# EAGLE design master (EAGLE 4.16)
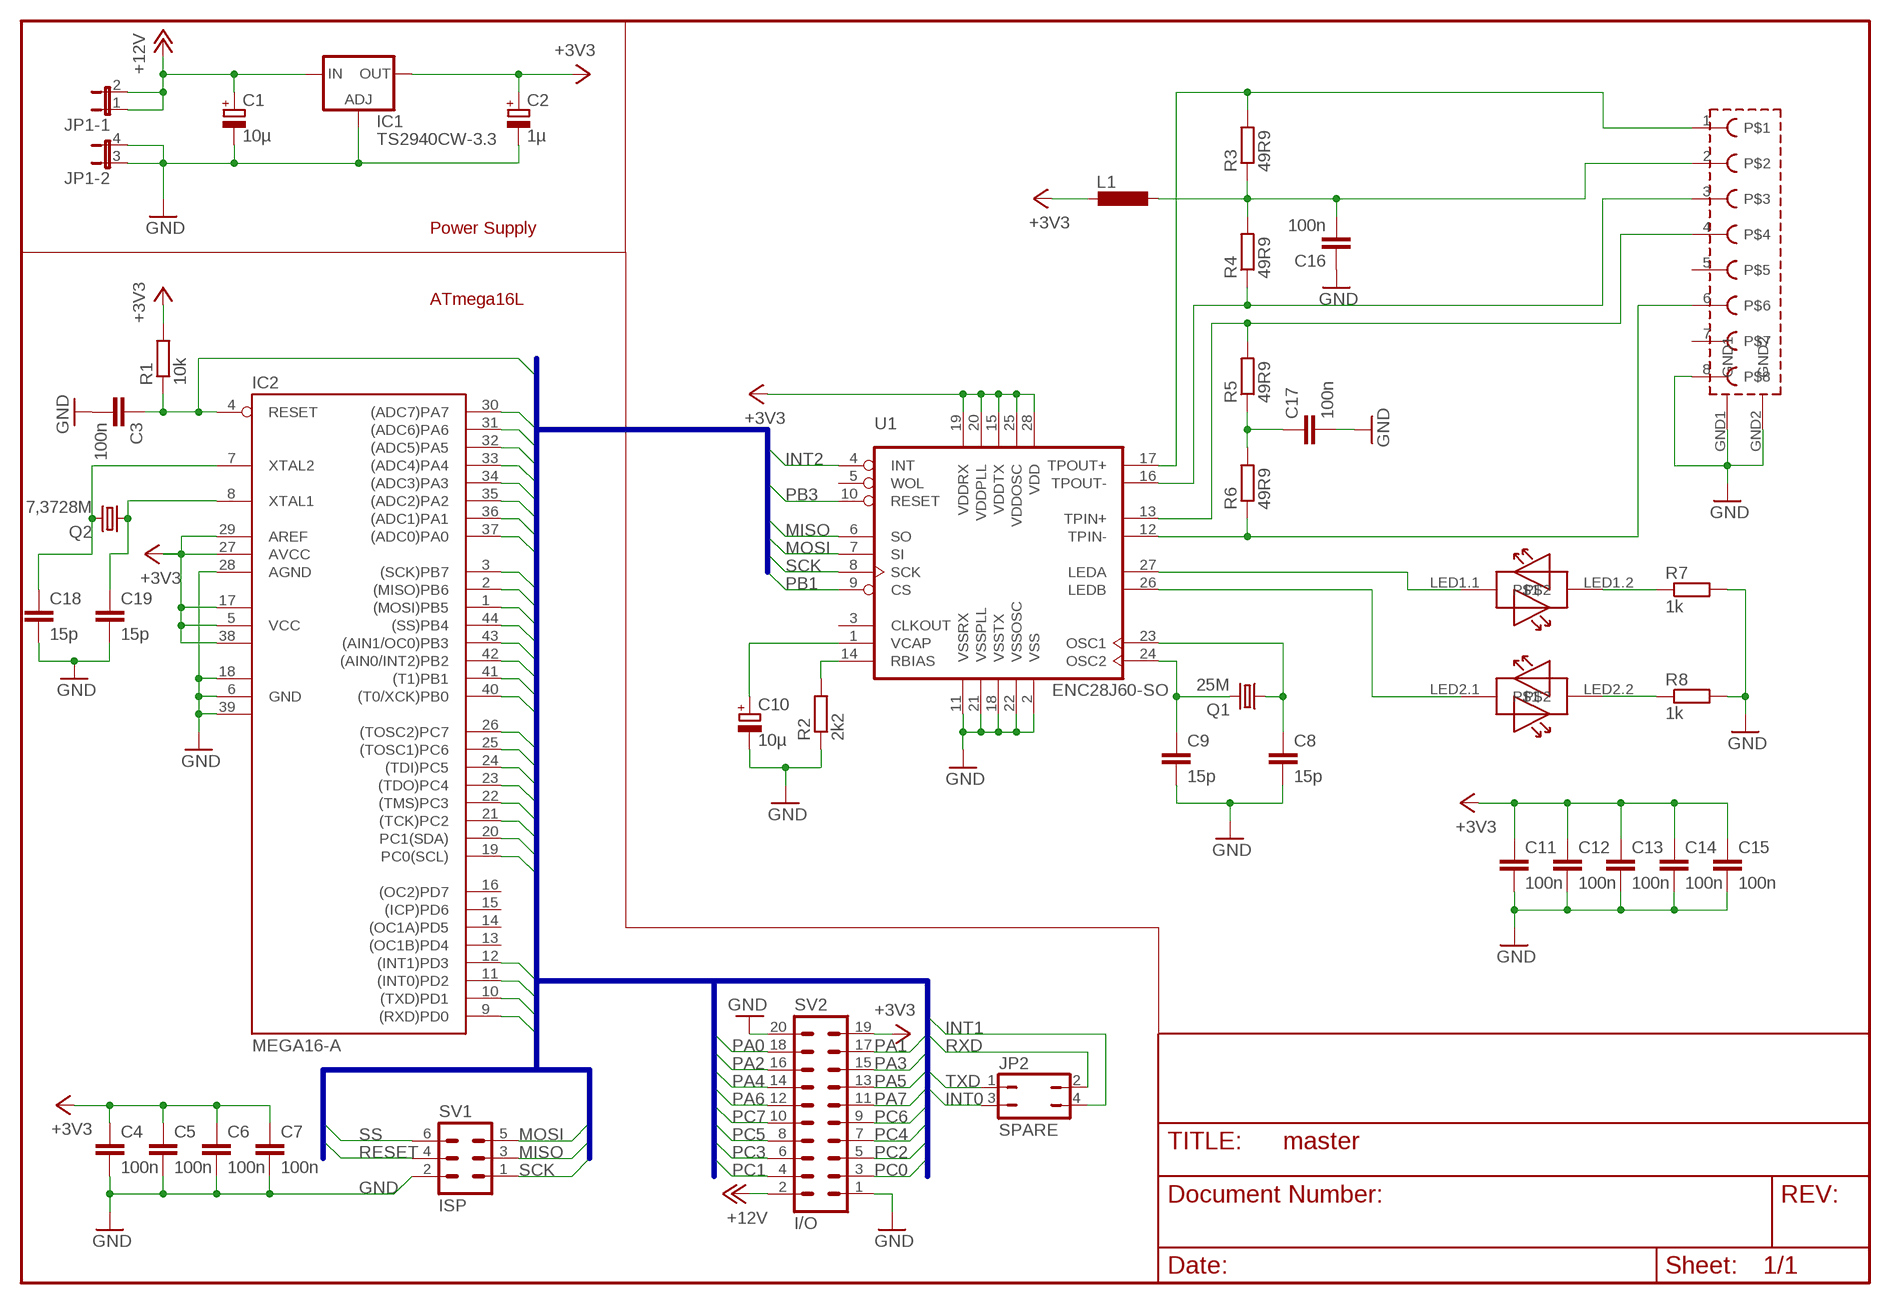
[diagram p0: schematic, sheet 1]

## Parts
C1  10µ  CPOL-EUSMCD  [SMC_D]
C2  1µ  CPOL-EUSMCA  [SMC_A]
C3  100n  C-EUC0805K  [C0805K]
C4  100n  C-EUC0805K  [C0805K]
C5  100n  C-EUC0805K  [C0805K]
C6  100n  C-EUC0805K  [C0805K]
C7  100n  C-EUC0805K  [C0805K]
C8  15p  C-EUC0603  [C0603]
C9  15p  C-EUC0603  [C0603]
C10  10µ  CPOL-EUSMCA  [SMC_A]
C11  100n  C-EUC0805K  [C0805K]
C12  100n  C-EUC0805K  [C0805K]
C13  100n  C-EUC0805K  [C0805K]
C14  100n  C-EUC0805K  [C0805K]
C15  100n  C-EUC0805K  [C0805K]
C16  100n  C-EUC0805K  [C0805K]
C17  100n  C-EUC0805K  [C0805K]
C18  15p  C-EUC0603  [C0603]
C19  15p  C-EUC0603  [C0603]
IC1  TS2940CW-3.3  LM317MBSTT3  [SOT223]
IC2  MEGA16-A  [TQFP44]
JP1  JP2QE  [JP2Q]
JP2  SPARE  JP2Q  [JP2Q]
L1  L-EUL2012C  [L2012C]
Q1  25M  CRYTALHC49UP  [HC49UP]
Q2  7,3728M  CRYTALHC49UP  [HC49UP]
R1  10k  R-EU_R0805  [R0805]
R2  2k2  R-EU_R0805  [R0805]
R3  49R9  R-EU_R0805  [R0805]
R4  49R9  R-EU_R0805  [R0805]
R5  49R9  R-EU_R0805  [R0805]
R6  49R9  R-EU_R0805  [R0805]
R7  1k  R-EU_R0805  [R0805]
R8  1k  R-EU_R0805  [R0805]
SV1  ISP  MA03-2  [MA03-2]
SV2  I/O  MA10-2  [MA10-2]
U1  ENC28J60-SO  [SO28W]
U$1  MAGJACK  [MAGJACK]

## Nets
+3V3: C2.+ C4.1 C5.1 C6.1 C7.1 C11.1 C12.1 C13.1 C14.1 C15.1 IC1.4(OUT) IC2.5(VCC) IC2.17(VCC1) IC2.27(AVCC) IC2.29(AREF) IC2.38(VCC2) L1.2 R1.2 SV2.19 U1.15(VDDTX) U1.19(VDDRX) U1.20(VDDPLL) U1.25(VDDOSC) U1.28(VDD)
+12V: C1.+ IC1.3(IN) JP1.1 JP1.2 SV2.2
GND: C1.- C2.- C3.2 C4.2 C5.2 C6.2 C7.2 C8.2 C9.2 C10.- C11.2 C12.2 C13.2 C14.2 C15.2 C16.1 C17.2 C18.2 C19.2 IC1.1(ADJ) IC2.6(GND) IC2.18(GND1) IC2.28(AGND) IC2.39(GND2) JP1.3 JP1.4 R2.1 R7.2 R8.2 SV1.2 SV2.1 SV2.20 U1.2(VSS) U1.11(VSSRX) U1.18(VSSTX) U1.21(VSSPLL) U1.22(VSSOSC) U$1.8 U$1.GND1 U$1.GND2
INT0: IC2.11((INT0)PD2) JP2.3
INT1: IC2.12((INT1)PD3) JP2.4
INT2: IC2.42((AIN0/INT2)PB2) U1.4(INT)
MISO: IC2.2((MISO)PB6) SV1.3 U1.6(SO)
MOSI: IC2.1((MOSI)PB5) SV1.5 U1.7(SI)
N$1: C18.1 IC2.7(XTAL2) Q2.2
N$2: R2.2 U1.14(RBIAS)
N$3: C10.+ U1.1(VCAP)
N$4: R5.2 U1.13(TPIN+) U$1.4
N$5: C9.1 Q1.2 U1.24(OSC2)
N$6: C8.1 Q1.1 U1.23(OSC1)
N$7: C17.1 R5.1 R6.2
N$8: R4.1 U1.16(TPOUT-) U$1.3
N$9: R3.2 U1.17(TPOUT+) U$1.1
N$10: C16.2 L1.1 R3.1 R4.2 U$1.2
N$11: R7.1 U$1.LED1.2
N$12: R8.1 U$1.LED2.2
N$13: U1.27(LEDA) U$1.LED1.1
N$14: U1.26(LEDB) U$1.LED2.1
N$15: C19.1 IC2.8(XTAL1) Q2.1
PA0: IC2.37((ADC0)PA0) SV2.18
PA1: IC2.36((ADC1)PA1) SV2.17
PA2: IC2.35((ADC2)PA2) SV2.16
PA3: IC2.34((ADC3)PA3) SV2.15
PA4: IC2.33((ADC4)PA4) SV2.14
PA5: IC2.32((ADC5)PA5) SV2.13
PA6: IC2.31((ADC6)PA6) SV2.12
PA7: IC2.30((ADC7)PA7) SV2.11
PB0: IC2.40((T0/XCK)PB0)
PB1: IC2.41((T1)PB1) U1.9(CS)
PB3: IC2.43((AIN1/OC0)PB3) U1.10(RESET)
PC0: IC2.19(PC0(SCL)) SV2.3
PC1: IC2.20(PC1(SDA)) SV2.4
PC2: IC2.21((TCK)PC2) SV2.5
PC3: IC2.22((TMS)PC3) SV2.6
PC4: IC2.23((TDO)PC4) SV2.7
PC5: IC2.24((TDI)PC5) SV2.8
PC6: IC2.25((TOSC1)PC6) SV2.9
PC7: IC2.26((TOSC2)PC7) SV2.10
RESET: C3.1 IC2.4(RESET) R1.1 SV1.4
RXD: IC2.9((RXD)PD0) JP2.2
SCK: IC2.3((SCK)PB7) SV1.1 U1.8(SCK)
SS: IC2.44((SS)PB4) SV1.6
TXD: IC2.10((TXD)PD1) JP2.1
X1: R6.1 U1.12(TPIN-) U$1.6
Unconnected: IC2.13((OC1B)PD4) IC2.14((OC1A)PD5) IC2.15((ICP)PD6) IC2.16((OC2)PD7) U1.3(CLKOUT) U1.5(WOL) U$1.5 U$1.7

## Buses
MISO,MOSI,SS,SCK,RESET,PB0,PB1,PB3,INT0,INT1,INT2,TXD,RXD,PA[0..7],PC[0..7]

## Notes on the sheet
- Power Supply
- ATmega16L

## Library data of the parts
C1 C2 C10 = rcl:CPOL-EU: POLARIZED CAPACITOR, European symbol
C3-C9 C11-C19 = rcl:C-EU: CAPACITOR, European symbol
IC1 = v-reg:LM317?*: 500 mA Adjustable Output Positive Voltage Regulator Source: http://www.onsemi.co.jp .. LM317M-D.PDF
IC2 = atmel:MEGA16: MICROCONTROLLER 16 Kbytes FLASH 1 kbytes SRAM 512 bytes EEPROM USART 8-channel 10 bit ADC Source: avr.lbr
JP1 = jumper:JP2QE: JUMPER
JP2 = jumper:JP2Q: JUMPER
L1 = rcl:L-EU: INDUCTOR, European symbol
Q1 Q2 = crystal:CRYTAL: CRYSTAL
R1-R8 = rcl:R-EU_: RESISTOR, European symbol
SV1 = con-lstb:MA03-2: PIN HEADER
SV2 = con-lstb:MA10-2: PIN HEADER
U1 = microchip-enc28j60:ENC28J60-*: Microchip 10Mbit Eth. contoller with SPI interface
U$1 = magjack:MAGJACK

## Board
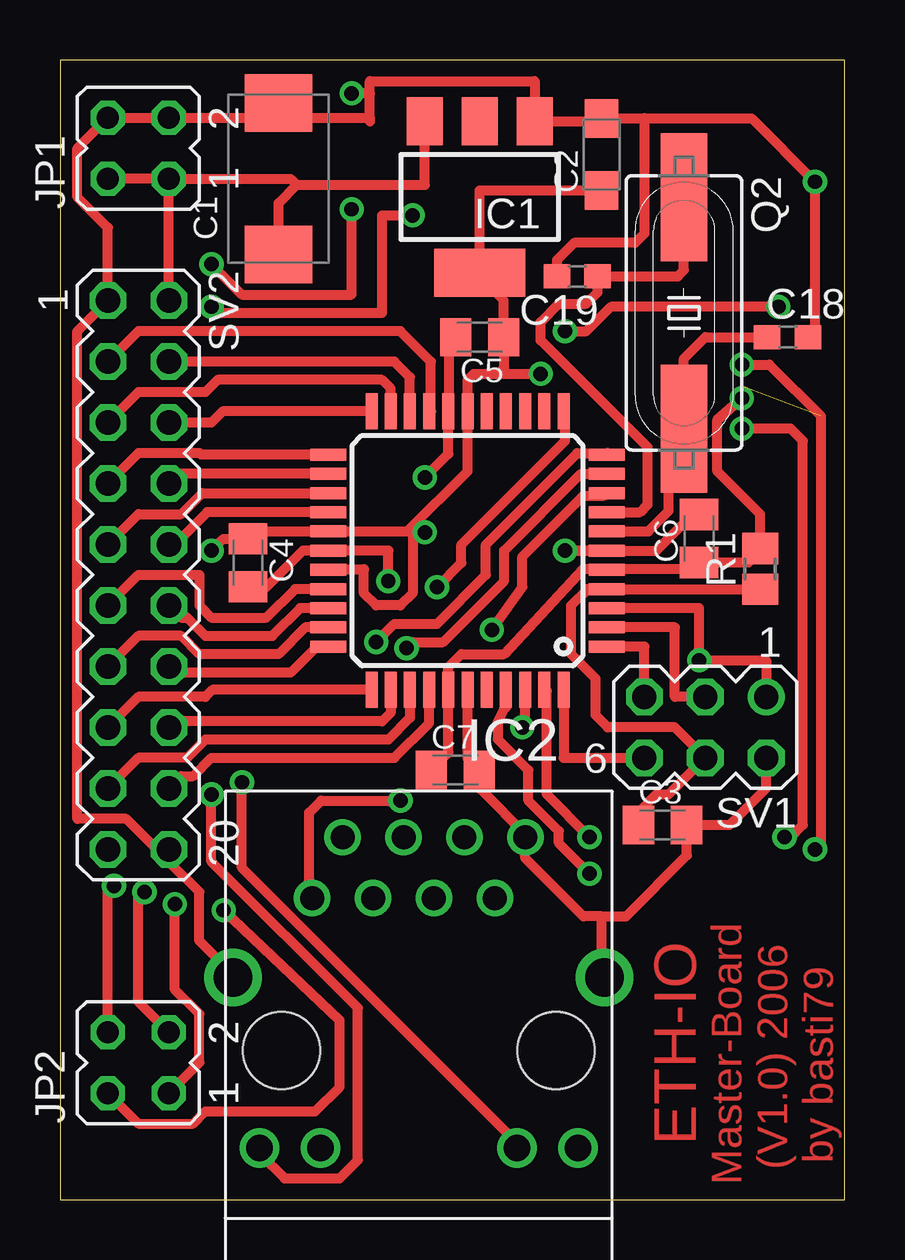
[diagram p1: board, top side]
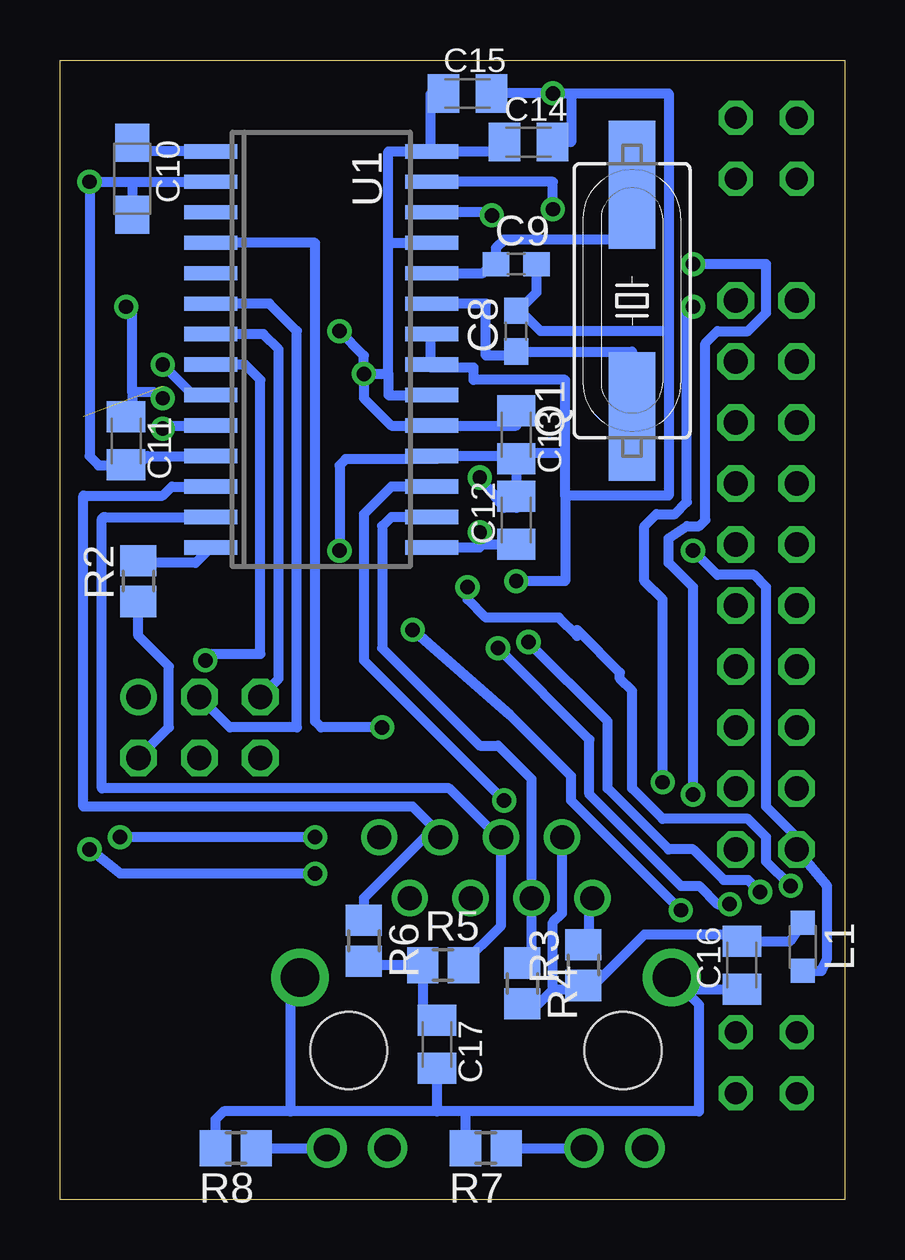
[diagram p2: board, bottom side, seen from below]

Size 32.69 x 47.49 mm. Coordinates in mm from the lower left corner, seen from the top.
Outline: 0,0 32.69,0 32.69,47.49 0,47.49 0,0
Copper layers (1*16): Top 0.035mm / dielectric 1.5mm / Bottom 0.035mm
Design rules "default": minimum track width 10mil, minimum drill 20mil, track to track 8mil, track to pad 8mil, pad to pad 8mil, via to via 8mil, smd to smd 8mil, copper to edge 20mil, drill to drill 8mil, minimum pad ring 10mil, minimum via ring 8mil, stop-mask expansion 4mil, vias tented up to drill 0mil, thermal gap 10mil

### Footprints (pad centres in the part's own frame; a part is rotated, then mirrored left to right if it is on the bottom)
SMC_D = smd 2.4 x 2.8: + -3.15,0; - 3.15,0
SMC_A = smd 1.6 x 1.4: + -1.5,0; - 1.5,0
C0805K = smd 1.3 x 1.6: 1 -1,0; 2 1,0
C0603 = smd 1.1 x 1: 1 -0.85,0; 2 0.85,0
SOT223 = smd 1.5 x 2: 1 -2.3,-3.15; 2 0,-3.15; 3 2.3,-3.15 | smd 3.8 x 2: 4 0,3.15
TQFP44 = smd 1.5 x 0.5: 1 -5.8,4; 2 -5.8,3.2; 3 -5.8,2.4; 4 -5.8,1.6; 5 -5.8,0.8; 6 -5.8,0; 7 -5.8,-0.8; 8 -5.8,-1.6; 9 -5.8,-2.4; 10 -5.8,-3.2; 11 -5.8,-4; 23 5.8,-4; 24 5.8,-3.2; 25 5.8,-2.4; 26 5.8,-1.6; 27 5.8,-0.8; 28 5.8,0; 29 5.8,0.8; 30 5.8,1.6; 31 5.8,2.4; 32 5.8,3.2; 33 5.8,4 | smd 0.5 x 1.5: 12 -4,-5.8; 13 -3.2,-5.8; 14 -2.4,-5.8; 15 -1.6,-5.8; 16 -0.8,-5.8; 17 0,-5.8; 18 0.8,-5.8; 19 1.6,-5.8; 20 2.4,-5.8; 21 3.2,-5.8; 22 4,-5.8; 34 4,5.8; 35 3.2,5.8; 36 2.4,5.8; 37 1.6,5.8; 38 0.8,5.8; 39 0,5.8; 40 -0.8,5.8; 41 -1.6,5.8; 42 -2.4,5.8; 43 -3.2,5.8; 44 -4,5.8
JP2Q = drill 0.914 octagon: 1 -1.27,-1.27; 2 -1.27,1.27; 3 1.27,-1.27; 4 1.27,1.27
L2012C = smd 1 x 1: 1 -1,0; 2 1,0
HC49UP = smd 5.334 x 1.93: 1 -4.826,0; 2 4.826,0
R0805 = smd 1.3 x 1.5: 1 -0.85,0; 2 0.85,0
MA03-2 = drill 1.016 round: 1 -2.54,-1.27 | drill 1.016 octagon: 2 -2.54,1.27; 3 0,-1.27; 4 0,1.27; 5 2.54,-1.27; 6 2.54,1.27
MA10-2 = drill 1.016 octagon: 1 -11.43,-1.27; 2 -11.43,1.27; 3 -8.89,-1.27; 4 -8.89,1.27; 5 -6.35,-1.27; 6 -6.35,1.27; 7 -3.81,-1.27; 8 -3.81,1.27; 9 -1.27,-1.27; 10 -1.27,1.27; 11 1.27,-1.27; 12 1.27,1.27; 13 3.81,-1.27; 14 3.81,1.27; 15 6.35,-1.27; 16 6.35,1.27; 17 8.89,-1.27; 18 8.89,1.27; 19 11.43,-1.27; 20 11.43,1.27
SO28W = smd 0.6 x 2.2: 1 -8.255,-4.6; 2 -6.985,-4.6; 3 -5.715,-4.6; 4 -4.445,-4.6; 5 -3.175,-4.6; 6 -1.905,-4.6; 7 -0.635,-4.6; 8 0.635,-4.6; 9 1.905,-4.6; 10 3.175,-4.6; 11 4.445,-4.6; 12 5.715,-4.6; 13 6.985,-4.6; 14 8.255,-4.6; 15 8.255,4.6; 16 6.985,4.6; 17 5.715,4.6; 18 4.445,4.6; 19 3.175,4.6; 20 1.905,4.6; 21 0.635,4.6; 22 -0.635,4.6; 23 -1.905,4.6; 24 -3.175,4.6; 25 -4.445,4.6; 26 -5.715,4.6; 27 -6.985,4.6; 28 -8.255,4.6
MAGJACK = drill 1 round: 1 -4.445,6.35; 2 -3.175,8.89; 3 -1.905,6.35; 4 -0.635,8.89; 5 0.635,6.35; 6 1.905,8.89; 7 3.175,6.35; 8 4.445,8.89 | drill 1.6 round: GND1 -7.747,3.048; GND2 7.747,3.048 | drill 1.1 round: LED1.1 -6.629,-4.064; LED1.2 -4.089,-4.064; LED2.1 4.089,-4.064; LED2.2 6.629,-4.064 | hole 3.2: -5.715,0; 5.715,0

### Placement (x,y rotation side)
C1  9.11,42.54 90 top
C2  22.57,43.56 90 top
C3  25.11,15.62 0 top
C4  7.84,26.54 270 top
C5  17.49,35.94 180 top
C6  26.63,27.55 90 top
C7  16.47,17.9 0 top
C8  13.68,36.19 90 bottom
C9  13.68,38.98 0 bottom
C10  29.68,42.54 270 bottom
C11  29.93,31.62 270 bottom
C12  13.68,28.32 90 bottom
C13  13.68,31.87 270 bottom
C14  13.17,44.06 0 bottom
C15  15.71,46.1 0 bottom
C16  4.28,9.77 90 bottom
C17  16.98,6.47 270 bottom
C18  30.31,35.94 0 top
C19  21.55,38.48 180 top
IC1  17.49,41.78 180 top
IC2  16.98,27.05 180 top
JP1  3.26,43.81 90 top
JP2  3.26,5.71 90 top
L1  1.74,10.54 270 bottom
Q1  8.85,37.46 90 bottom
Q2  26,36.95 270 top
R1  29.17,26.28 90 top
R2  29.43,25.78 90 bottom
R3  10.88,9.77 90 bottom
R4  13.42,9.01 270 bottom
R5  16.73,9.77 0 bottom
R6  20.03,10.79 270 bottom
R7  14.95,2.15 180 bottom
R8  25.36,2.15 180 bottom
SV1  26.89,19.68 180 top
SV2  3.26,26.03 270 top
U1  21.81,35.43 270 bottom
U$1  14.95,6.22 0 top

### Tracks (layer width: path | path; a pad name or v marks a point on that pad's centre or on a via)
+3V3  (via drill 0.6)
  Top 0.406: C2.+ 17.49,42.06 IC1.4 17.49,38.48 18.49,37.48 C5.1 18.5,35.94 18.5,34.67 18.38,34.54 | IC2.5 22.78,26.28 22.82,26.28 | 18.38,34.54 18.25,34.41 17.23,34.41 16.98,34.16 IC2.17 16.98,30.35 14.48,27.85 | 18.38,34.54 18.5,34.54 18.5,34.41 v20.03,34.41 | 14.48,27.85 IC2.27 7.87,27.85 7.58,27.55 C4.1 6.8,27.54 v6.31,27.05 | 14.48,27.85 14.69,27.85 | 14.69,27.85 15.16,27.85 v15.2,27.81 | 22.82,26.28 IC2.5 | 16.18,18.63 15.96,18.41 C7.1 15.46,17.9 | 16.18,18.63 IC2.38 16.18,22.18 16.73,22.73 18.5,22.73 21.81,26.28 23.08,26.28 | 15.46,17.9 16.18,18.63 | 12.66,26.25 12.66,25.27 13.17,24.76 14.19,24.76 14.69,25.27 14.69,27.85 | 15.46,17.9 15.58,17.77 | 23.08,26.28 22.82,26.28 | 23.08,26.28 26.38,26.28 26.63,26.54 C6.1 28.68,26.55 29.17,27.05 | 23.08,26.28 23.04,26.25 IC2.5 | 29.17,27.05 R1.2 | 29.17,27.05 29.17,28.57 27.39,30.35 27.39,32.51 v28.41,33.4 | v29.93,37.21 22.95,37.21 21.93,36.19 v21.04,36.19 | 12.66,26.25 IC2.29 | 12.66,26.25 12.66,26.28
  Bottom 0.406: 13.68,32.89 C13.1 13.68,32.25 U1.19 18.88,32.25 20.03,33.4 v20.03,34.41 | U1.28 19.01,43.68 19.01,39.87 | 19.01,39.87 U1.25 | 19.01,34.41 19.01,39.87 | U1.28 17.23,43.68 17.23,46.1 C15.1 | L1.2 0.96,9.54 0.72,10.03 0.72,13.08 SV2.19 1.99,15.11 3.26,16.38 3.26,25.52 3.77,26.03 5.3,26.03 v6.31,27.05 | U1.20 19.01,33.52 19.01,34.41 | v20.03,34.41 19.01,34.41 | C14.1 14.19,44.06 14.57,43.68 U1.28 | 29.43,32.63 C11.1 29.93,32.63 29.68,32.89 29.68,33.65 | v29.93,37.21 29.68,36.95 29.68,33.65 | 15.2,27.32 C12.1 | v15.2,27.81 15.2,27.32 | U1.15 15.2,27.17 15.2,27.32 | v28.41,33.4 28.79,33.65 29.68,33.65 | v20.03,34.41 20.03,35.17 v21.04,36.19
+12V
  Top 0.406: JP1.1 JP1.2 | IC1.3 15.2,44.93 15.2,42.29 9.87,42.29 | JP1.1 9.61,42.54 9.87,42.29 | SV2.2 JP1.1 | C1.+ 9.11,41.52 9.87,42.29
GND  (via drill 0.6)
  Top 0.406: 12.92,45.08 12.92,46.1 | 12.92,45.08 12.92,44.93 | 12.92,46.1 12.92,46.6 19.77,46.6 19.77,44.93 IC1.1 22.57,44.93 C2.- | C2.- 22.57,45.08 | 7.58,25.52 C4.2 7.33,25.52 8.6,25.52 10.12,27.05 IC2.28 13.68,27.05 v13.68,25.78 | 12.92,46.1 v12.15,46.1 | 22.57,27.05 21.3,27.05 | 16.22,35.67 C5.2 16.47,35.94 16.22,35.68 16.22,32.85 IC2.18 16.18,31.07 v15.2,30.09 | C1.- 9.11,45.59 8.6,45.08 | 8.6,45.08 JP1.3 JP1.4 0.72,43.81 0.72,41.78 1.99,40.51 SV2.1 0.72,36.19 0.72,15.87 2.76,15.87 4.03,14.6 SV2.20 4.53,14.09 5.8,12.82 5.8,10.79 7.33,9.27 U$1.GND1 | 8.6,45.08 12.92,45.08 | 22.57,27.05 IC2.6 24.85,27.05 26.36,28.55 C6.2 | v21.04,27.05 22.57,27.05 | 26.12,15.62 C3.2 | 26.12,15.62 26.12,14.35 23.58,11.81 22.57,11.81 | IC2.39 16.98,18.41 17.49,17.9 | 17.49,17.9 C7.2 | 17.49,17.9 17.49,17.14 19.52,15.11 U$1.8 19.39,14.22 21.81,11.81 22.57,11.81 | 22.57,11.81 22.57,9.27 U$1.GND2 | 26.12,15.62 27.9,15.62 29.43,17.14 SV1.2 | C2.- 24.35,45.06 | 24.35,45.06 28.81,45.06 v31.46,42.41 31.46,36.19 31.2,35.94 C18.2 | C19.2 20.7,39.15 21.42,39.87 23.96,39.87 24.35,40.25 24.35,45.06 | 24.35,45.06 24.35,45.08
  Bottom 0.406: 13.68,30.98 C13.2 13.68,30.86 | 13.68,30.98 U1.18 17.11,30.98 16.98,30.86 20.79,30.86 21.04,30.6 v21.04,27.05 | 13.68,31.11 13.68,30.98 | 13.68,30.86 13.68,28.82 | 17.23,34.79 17.23,34.67 15.46,34.67 15.46,34.16 11.65,34.16 11.65,31.11 | 17.23,34.79 U1.21 | U1.22 17.23,36.06 17.23,34.79 | 29.68,42.41 U1.2 | 29.68,42.41 C10.- | 11.65,31.11 13.68,31.11 | 13.68,31.11 13.68,30.86 | 11.65,29.33 11.65,31.11 | C15.2 v12.15,46.1 11.39,46.1 | 15.71,3.68 6.06,3.68 6.06,8.12 U$1.GND1 7.07,9.27 6.58,8.77 C16.1 | 15.71,3.68 16.98,3.68 | 16.98,3.68 23.08,3.68 | U$1.GND2 22.57,9.27 23.08,8.76 23.08,3.68 | 16.98,3.68 C17.2 | U1.11 29.04,30.98 29.43,30.6 C11.2 29.93,30.6 30.06,30.47 30.19,30.6 31.08,30.6 31.46,30.98 v31.46,42.41 | 13.68,28.82 C12.2 | v15.2,30.09 14.19,28.82 13.68,28.82 | R2.1 29.43,23.49 28.16,22.22 28.16,19.68 SV1.2 | R7.2 15.8,3.59 15.71,3.68 | R8.2 26.21,3.34 25.87,3.68 23.08,3.68 | C14.2 11.39,44.06 11.39,46.1 | 13.68,36.95 C8.2 | C9.2 12.83,37.8 13.68,36.95 | 13.68,36.95 13.42,36.95 12.66,36.19 7.33,36.19 | 11.65,29.33 7.33,29.33 7.33,36.19 | 7.33,36.19 7.33,46.1 11.39,46.1 | v13.68,25.78 11.65,25.78 11.65,29.33 | v31.46,42.41 31.58,42.41 | v31.46,42.41 29.68,42.41
INT0  (via drill 0.6)
  Top 0.406: JP2.3 3.26,8.25 3.26,12.57 v3.52,12.82 | IC2.11 22.78,31.07 22.82,31.11 21.55,31.11 17.74,27.3 17.74,26.03 15.71,24 13.93,24 v13.17,23.24
  Bottom 0.406: v13.17,23.24 9.87,19.93 9.87,17.14 7.33,14.6 6.31,14.6 5.04,13.33 4.03,13.33 v3.52,12.82
INT1  (via drill 0.6)
  Top 0.406: JP2.4 1.99,12.82 v2.25,13.08 | IC2.12 20.98,32.7 21.04,32.63 21.04,31.62 16.73,27.3 16.73,26.54 v15.71,25.52
  Bottom 0.406: v2.25,13.08 3.26,14.09 3.26,15.11 4.03,15.87 7.58,15.87 8.85,17.14 8.85,21.2 9.36,21.71 9.36,21.97 11.01,23.62 | 11.01,23.62 11.14,23.74 | v15.71,25.52 15.71,25.01 14.95,24.25 11.9,24.25 11.14,23.49 11.01,23.62
INT2  (via drill 0.6)
  Top 0.406: 19.27,19.93 v19.27,19.68 19.38,19.79 IC2.42
  Bottom 0.406: v19.27,19.68 21.81,19.68 22.06,19.93 22.06,39.87 U1.4
MISO
  Top 0.406: IC2.2 25.62,23.85 25.62,20.95 SV1.3
  Bottom 0.406: U1.6 23.96,37.33 22.82,36.19 22.82,19.68 25.62,19.68 SV1.3
MOSI
  Top 0.406: IC2.1 24.35,23.05 SV1.5
  Bottom 0.406: U1.7 24.22,36.06 23.58,35.43 23.58,21.71 SV1.5
N$1
  Top 0.406: C18.1 26.89,35.94 26,35.05 Q2.2 25.36,31.49 25.36,28.7 24.51,27.85 IC2.7
N$2
  Bottom 0.406: R2.2 29.43,26.54 27.04,26.54 U1.14
N$3
  Bottom 0.406: 29.68,44.06 C10.+ 29.68,43.68 U1.1
N$4
  Bottom 0.406: R5.2 15.96,9.77 14.31,11.43 U$1.4 14.44,15.11 16.47,17.14 30.95,17.14 30.95,28.32 arc90 30.82,28.44 U1.13
N$5
  Bottom 0.406: Q1.2 9.11,42.03 9.11,40.25 9.36,40 14.19,40 14.53,39.66 C9.1 14.69,38.98 15.08,38.6 U1.24
N$6
  Bottom 0.406: U1.23 14.95,37.33 14.95,35.17 13.68,35.17 C8.1 | C8.1 13.68,35.43 | 8.85,32.38 Q1.1 8.85,35.34 C8.1
N$7
  Bottom 0.406: R6.2 20.03,10.03 19.77,9.77 R5.1 17.58,7.83 17.22,7.47 C17.1
N$8
  Bottom 0.406: U1.16 18.88,28.44 19.27,28.06 19.27,22.98 15.2,18.92 14.44,18.92 13.04,17.52 U$1.3 13.04,10.16 13.42,9.77 R4.1
N$9  (via drill 0.6)
  Top 0.406: v14.19,16.63 10.88,16.63 10.38,16.12 10.38,12.82 10.63,12.57 U$1.1
  Bottom 0.406: U1.17 18.88,29.71 20.03,28.57 20.03,22.47 v14.19,16.63 | U$1.1 10.63,12.57 10.63,10.79 11.14,10.28 R3.2
N$10
  Bottom 0.406: L1.1 1.74,11.55 2.26,10.77 C16.2 4.28,10.79 4.53,11.04 8.34,11.04 10.38,9.01 10.88,9.01 R3.1 | R4.2 12.75,8.16 12.15,8.76 | 12.15,8.76 12.15,11.55 11.77,11.93 U$1.2 | R3.1 11.14,8.76 12.15,8.76 | R3.1 10.88,8.76
N$11
  Bottom 0.406: R7.1 U$1.LED1.2
N$12
  Bottom 0.406: 21.55,2.15 U$1.LED2.2 R8.1
N$13  (via drill 0.6)
  Top 0.406: v12.15,41.27 12.15,37.71 7.58,37.71 v6.31,38.98 | v6.31,16.89 6.31,14.09 12.41,8 12.41,1.65 11.65,0.88 9.36,0.88 8.32,1.92 U$1.LED1.1 8.34,2.15
  Bottom 0.406: U1.27 12.15,42.41 v12.15,41.27 | v6.31,38.98 3.26,38.98 3.26,36.95 4.03,36.19 5.3,36.19 5.8,35.68 5.8,28.32 6.06,28.06 6.57,28.06 7.33,27.55 7.33,26.54 6.31,25.52 v6.31,16.89
N$14  (via drill 0.6)
  Top 0.406: v14.69,41.02 13.42,41.02 13.42,36.95 6.31,36.95 v6.31,37.21 | 19.01,2.15 U$1.LED2.1 19.04,2.38 7.58,13.84 v7.58,17.39
  Bottom 0.406: U1.26 14.69,41.14 v14.69,41.02 | v7.58,17.39 7.58,25.01 8.34,25.78 8.34,28.06 7.84,28.57 7.07,28.57 6.57,29.08 6.57,37.21 v6.31,37.21
N$15
  Top 0.406: Q2.1 26,38.73 25.74,38.48 C19.1 22.4,37.8 21.93,37.33 20.79,37.33 20.03,36.57 20.03,35.81 24.47,31.36 24.47,28.95 24.17,28.65 IC2.8
PA0
  Top 0.406: IC2.37 15.38,19.86 13.93,18.41 6.31,18.41 5.55,17.65 5.04,17.65 SV2.18
PA1
  Top 0.406: IC2.36 14.58,20.07 13.68,19.17 6.06,19.17 5.3,18.41 3.26,18.41 SV2.17
PA2
  Top 0.406: IC2.35 13.78,20.29 13.42,19.93 4.79,19.93 SV2.16
PA3
  Top 0.406: IC2.34 6.35,21.25 6.06,20.95 3.26,20.95 SV2.15
PA4
  Top 0.406: IC2.33 10.69,23.05 9.61,21.97 4.79,21.97 SV2.14
PA5
  Top 0.406: IC2.32 10.22,23.85 9.11,22.73 5.8,22.73 5.04,23.49 3.26,23.49 SV2.13
PA6
  Top 0.406: SV2.12 5.04,24.25 5.3,24.25 6.06,23.49 8.85,23.49 10.01,24.65 IC2.31
PA7
  Top 0.406: SV2.11 3.26,26.03 5.8,26.03 5.8,24.76 6.31,24.25 8.6,24.25 9.79,25.45 IC2.30
PB1  (via drill 0.6)  (2 unrouted)
  Top 0.406: IC2.41 18.58,20.52 18.5,20.44 18.25,19.93 18.25,19.17 19.52,17.9 19.52,16.63 20.79,15.36 20.79,14.85 v22.06,13.58 | v31.46,14.6 31.71,14.85 31.71,32.63 29.55,34.79 v28.41,34.79
  Bottom 0.406: v22.06,13.58 30.19,13.58 v31.46,14.6 | U1.9 27.14,33.52 v28.41,34.79
PB3  (via drill 0.6)
  Top 0.406: IC2.43 20.22,21.2 20.28,21.2 20.28,16.89 v22.06,15.11 | v30.19,15.11 30.44,15.11 30.95,15.62 30.95,31.62 30.44,32.13 v28.41,32.13
  Bottom 0.406: v22.06,15.11 v30.19,15.11 | U1.10 28.28,32.25 v28.41,32.13
PC0
  Top 0.406: IC2.19 15.46,32.85 15.46,34.92 14.19,36.19 3.26,36.19 SV2.3
PC1
  Top 0.406: IC2.20 14.58,34.27 13.93,34.92 SV2.4
PC2
  Top 0.406: IC2.21 13.78,33.8 13.42,34.16 6.57,34.16 6.06,33.65 3.26,33.65 SV2.5
PC3
  Top 0.406: IC2.22 6.78,32.85 6.31,32.38 SV2.6
PC4
  Top 0.406: IC2.23 5.87,31.05 5.8,31.11 3.26,31.11 SV2.7
PC5
  Top 0.406: IC2.24 4.94,30.25 SV2.8
PC6
  Top 0.406: IC2.25 5.92,29.45 5.04,28.57 3.26,28.57 SV2.9
PC7
  Top 0.406: SV2.10 4.79,27.3 6.13,28.65 IC2.26
RESET
  Top 0.406: C3.1 24.11,16.14 24.85,16.89 25.36,16.89 SV1.4 25.62,19.68 22.82,19.68 22.31,20.19 22.31,21.71 21.3,22.73 21.3,24.76 21.98,25.45 IC2.4 29.1,25.45 29.17,25.52 R1.1
RXD  (via drill 0.6)
  Top 0.406: IC2.9 22.67,29.33 21.81,29.33 19.27,26.79 19.27,25.52 v18,23.74 | 9.69,9.34 v6.82,12.06 | 9.69,9.34 11.65,7.49 11.65,4.69 10.63,3.68 6.06,3.68 5.55,3.17 3.26,3.17 JP2.2 | 9.69,9.34
  Bottom 0.406: v18,23.74 13.93,20.19 11.39,17.65 11.39,16.63 v6.82,12.06
SCK  (via drill 0.6)
  Top 0.406: IC2.3 26.63,24.65 v26.63,22.47 29.43,22.47 SV1.1
  Bottom 0.406: U1.8 24.98,34.79 24.35,34.16 24.35,22.73 26.38,22.73 v26.63,22.47
SS
  Top 0.406: IC2.44 20.98,18.41 SV1.6
TXD  (via drill 0.6)
  Top 0.406: IC2.10 21.7,30.25 18.5,27.05 18.5,25.78 15.96,23.24 14.69,23.24 v14.44,22.98 | v4.79,12.31 4.79,8.76 5.8,7.74 5.8,5.71 JP2.1
  Bottom 0.406: v14.44,22.98 10.63,19.17 10.63,16.89 6.82,13.08 6.06,13.08 5.3,12.31 v4.79,12.31
X1
  Bottom 0.406: 20.03,11.55 R6.1 20.03,12.57 17.49,15.11 U$1.6 16.73,15.11 18,16.38 31.71,16.38 31.71,29.33 28.41,29.33 28.03,29.71 U1.12

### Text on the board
Top: ETH-IO | (V1.0) 2006 | by basti79 | Master-Board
